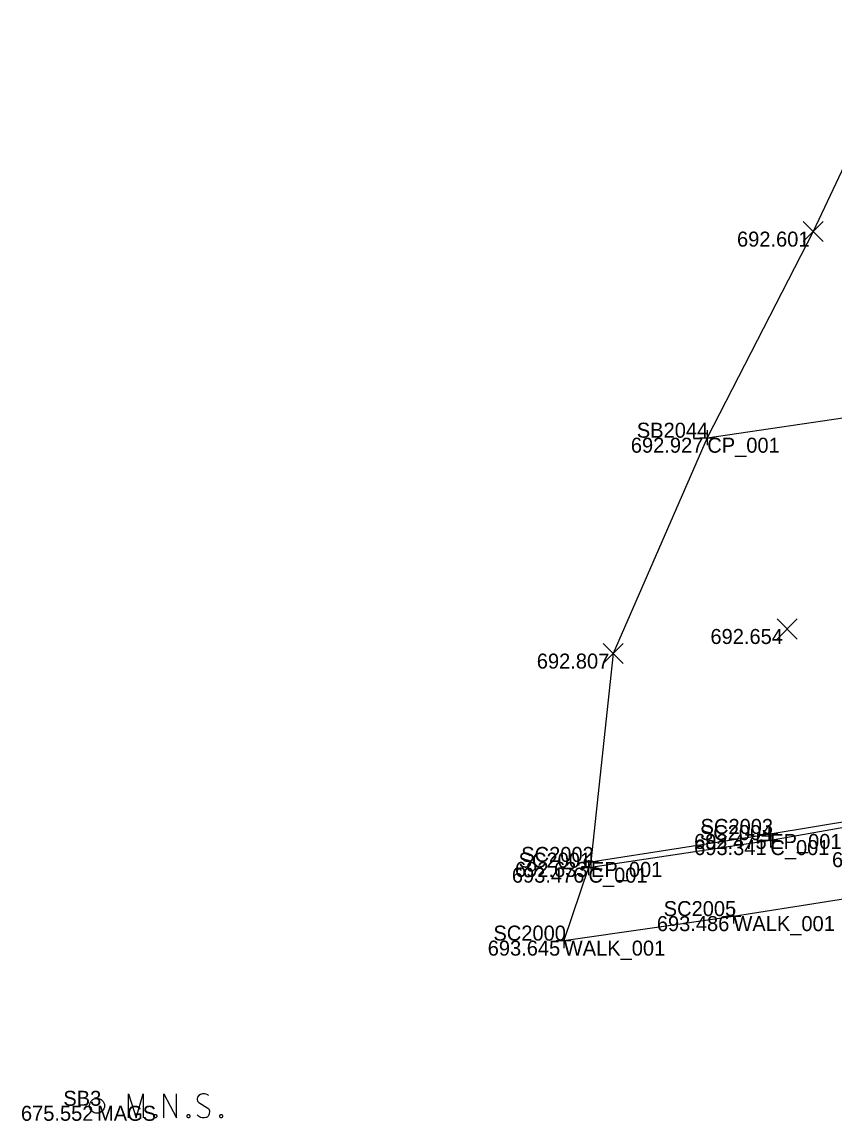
# Model space of a CAD drawing. Extents: x 1460264 to 1460899, y 578046 to 578200.
# Drawn here: x 1460774.7 to 1460828.8, y 578045.9 to 578119.1 of the extents above; entities that cross this region are included whole.
import ezdxf

# ---------------------------------------------------------------- set-up
doc = ezdxf.new("R2010")
doc.units = 0
for name, color, linetype in [('BR_X_SV_Beam_Seat', 7, 'Continuous'), ('PV_X_COP', 7, 'Continuous'), ('PV_X_Curb', 7, 'Continuous'), ('PV_X_EOP', 7, 'Continuous'), ('PV_X_Walk', 7, 'Continuous'), ('SC_Scratch1', 7, 'Continuous'), ('SV_P_Control_Cells_Set', 7, 'Continuous'), ('SV_X_Random_Point', 7, 'Continuous'), ('SV_X_Shot_Marker', 7, 'Continuous'), ('SV_X_Text_Comment', 7, 'Continuous'), ('SV_X_Text_Elevation', 7, 'Continuous'), ('SV_X_Text_Name', 7, 'Continuous')]:
    doc.layers.add(name, color=color, linetype=linetype)

msp = doc.modelspace()

# ---------------------------------------------------------------- linework, layer by layer
at = {"layer": 'PV_X_COP'}
msp.add_lwpolyline([(1460820.394, 578091.4), (1460835.169, 578093.562), (1460848.757, 578095.418)], dxfattribs=at)
at = {"layer": 'PV_X_Curb'}
msp.add_lwpolyline([(1460812.472, 578062.749), (1460824.599, 578064.587), (1460836.168, 578066.616)], dxfattribs=at)
at = {"layer": 'PV_X_EOP'}
msp.add_lwpolyline([(1460812.639, 578063.131), (1460824.588, 578064.995), (1460836.284, 578066.938)], dxfattribs=at)
at = {"layer": 'PV_X_Walk'}
msp.add_lwpolyline([(1460810.826, 578057.887), (1460822.136, 578059.521), (1460834.538, 578061.463)], dxfattribs=at)
at = {"layer": 'SC_Scratch1'}
msp.add_lwpolyline([(1460834.065, 578119.104), (1460827.459, 578105.134), (1460820.394, 578091.4), (1460814.124, 578077.014), (1460812.639, 578063.131), (1460812.472, 578062.749), (1460810.826, 578057.887), (1460822.136, 578059.521), (1460834.538, 578061.463)], dxfattribs=at)
at = {"layer": 'SV_P_Control_Cells_Set'}
for points in [[(1460781.8, 578046.079), (1460781.8, 578047.679), (1460782.307, 578046.079), (1460782.792, 578047.679), (1460782.792, 578046.079)], [(1460784.17, 578046.079), (1460784.17, 578047.679), (1460784.997, 578046.079), (1460784.997, 578047.679)], [(1460787.146, 578047.566), (1460787.124, 578047.591), (1460787.091, 578047.616), (1460786.992, 578047.654), (1460786.87, 578047.679), (1460786.782, 578047.679), (1460786.749, 578047.679), (1460786.606, 578047.641), (1460786.485, 578047.566), (1460786.407, 578047.465), (1460786.385, 578047.364), (1460786.385, 578047.289), (1460786.407, 578047.188), (1460786.496, 578047.1), (1460787.102, 578046.722), (1460787.157, 578046.671), (1460787.179, 578046.621), (1460787.201, 578046.545), (1460787.201, 578046.47), (1460787.19, 578046.394), (1460787.179, 578046.344), (1460787.157, 578046.281), (1460787.135, 578046.23), (1460787.113, 578046.193), (1460787.08, 578046.155), (1460787.047, 578046.13), (1460787.003, 578046.104), (1460786.97, 578046.092), (1460786.87, 578046.079), (1460786.716, 578046.079), (1460786.617, 578046.104), (1460786.474, 578046.193), (1460786.385, 578046.268)], [(1460783.564, 578046.294), (1460783.619, 578046.294), (1460783.652, 578046.268), (1460783.685, 578046.218), (1460783.685, 578046.155), (1460783.652, 578046.104), (1460783.619, 578046.079), (1460783.564, 578046.079), (1460783.53, 578046.104), (1460783.497, 578046.155), (1460783.497, 578046.218), (1460783.53, 578046.268), (1460783.564, 578046.294)], [(1460785.779, 578046.294), (1460785.834, 578046.294), (1460785.867, 578046.268), (1460785.9, 578046.218), (1460785.9, 578046.155), (1460785.867, 578046.104), (1460785.834, 578046.079), (1460785.779, 578046.079), (1460785.746, 578046.104), (1460785.713, 578046.155), (1460785.713, 578046.218), (1460785.746, 578046.268), (1460785.779, 578046.294)], [(1460787.962, 578046.294), (1460788.017, 578046.294), (1460788.05, 578046.268), (1460788.083, 578046.218), (1460788.083, 578046.155), (1460788.05, 578046.104), (1460788.017, 578046.079), (1460787.962, 578046.079), (1460787.929, 578046.104), (1460787.896, 578046.155), (1460787.896, 578046.218), (1460787.929, 578046.268), (1460787.962, 578046.294)]]:
    msp.add_lwpolyline(points, dxfattribs=at)
msp.add_circle((1460779.71, 578046.879), 0.497, dxfattribs=at)
at = {"layer": 'SV_X_Random_Point'}
for p, q in [((1460826.792, 578104.467), (1460828.126, 578105.802)), ((1460826.792, 578105.802), (1460828.126, 578104.467)), ((1460825.061, 578077.986), (1460826.394, 578079.321)), ((1460825.061, 578079.321), (1460826.394, 578077.986)), ((1460813.457, 578076.346), (1460814.79, 578077.681)), ((1460813.457, 578077.681), (1460814.79, 578076.346))]:
    msp.add_line(p, q, dxfattribs=at)
at = {"layer": 'SV_X_Shot_Marker'}
for p, q in [((1460820.394, 578091.9), (1460820.394, 578090.9)), ((1460819.894, 578091.4), (1460820.894, 578091.4)), ((1460820.394, 578091.4), (1460820.394, 578091.4)), ((1460824.088, 578064.995), (1460825.088, 578064.995)), ((1460824.588, 578065.495), (1460824.588, 578064.495)), ((1460824.588, 578064.995), (1460824.588, 578064.995)), ((1460824.599, 578065.087), (1460824.599, 578064.087)), ((1460824.099, 578064.587), (1460825.099, 578064.587)), ((1460824.599, 578064.587), (1460824.599, 578064.587)), ((1460812.639, 578063.631), (1460812.639, 578062.631)), ((1460811.972, 578062.749), (1460812.972, 578062.749)), ((1460812.139, 578063.131), (1460813.139, 578063.131)), ((1460812.472, 578063.249), (1460812.472, 578062.249)), ((1460812.472, 578062.749), (1460812.472, 578062.749)), ((1460812.639, 578063.131), (1460812.639, 578063.131)), ((1460822.136, 578060.021), (1460822.136, 578059.021)), ((1460821.636, 578059.521), (1460822.636, 578059.521)), ((1460822.136, 578059.521), (1460822.136, 578059.521)), ((1460810.826, 578058.387), (1460810.826, 578057.387)), ((1460810.326, 578057.887), (1460811.326, 578057.887)), ((1460810.826, 578057.887), (1460810.826, 578057.887))]:
    msp.add_line(p, q, dxfattribs=at)

# ---------------------------------------------------------------- texts
at = {"layer": 'BR_X_SV_Beam_Seat'}
msp.add_text('685.710', height=1, dxfattribs=at).set_placement((1460828.711, 578062.783))
at = {"layer": 'SV_X_Text_Comment'}
for s, p in [('CP_001', (1460820.394, 578090.4)), ('EP_001', (1460824.588, 578063.995)), ('C_001', (1460824.599, 578063.587)), ('C_001', (1460812.472, 578061.749)), ('EP_001', (1460812.639, 578062.131)), ('WALK_001', (1460822.136, 578058.521)), ('WALK_001', (1460810.826, 578056.887)), ('MAGS', (1460779.709, 578045.88))]:
    msp.add_text(s, height=1, dxfattribs=at).set_placement(p)
at = {"layer": 'SV_X_Text_Elevation'}
for s, p in [('692.601', (1460822.377, 578104.134)), ('692.927', (1460815.298, 578090.4)), ('692.654', (1460820.605, 578077.654)), ('692.807', (1460809.028, 578076.014)), ('692.475', (1460819.517, 578063.995)), ('693.341', (1460819.517, 578063.587)), ('693.476', (1460807.368, 578061.749)), ('692.633', (1460807.575, 578062.131)), ('693.486', (1460817.032, 578058.521)), ('693.645', (1460805.756, 578056.887)), ('675.552', (1460774.636, 578045.88))]:
    msp.add_text(s, height=1, dxfattribs=at).set_placement(p)
at = {"layer": 'SV_X_Text_Name'}
for s, p in [('SB2044', (1460815.696, 578091.4)), ('SC2004', (1460819.901, 578064.587)), ('SC2003', (1460819.948, 578064.995)), ('SC2002', (1460807.991, 578063.131)), ('SC2001', (1460807.815, 578062.749)), ('SC2005', (1460817.49, 578059.521)), ('SC2000', (1460806.137, 578057.887)), ('SB3', (1460777.464, 578046.88))]:
    msp.add_text(s, height=1, dxfattribs=at).set_placement(p)

doc.saveas('drawing.dxf')
